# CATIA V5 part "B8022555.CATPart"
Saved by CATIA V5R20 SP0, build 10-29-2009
Part number: B8022555
Revision: 6
Definition: design
Nomenclature: B8022555
Source: made
Description: NOT SPECIFIED
Bounding box of the stored display mesh (mm): x -22.5 to 22.5, y -22.5 to 22.5, z -10 to 55
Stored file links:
  C:\Users\Utente\Desktop\3D files B802\B8022555.CATPart
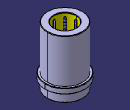
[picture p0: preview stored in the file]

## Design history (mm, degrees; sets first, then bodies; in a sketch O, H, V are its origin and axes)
Body1 "MANIFOLD_SOLID_BREP #38" (main body)
  Solid1: solid without history
Body2 "MANIFOLD_SOLID_BREP #76"
  Solid2: solid without history
Body3 "MANIFOLD_SOLID_BREP #114"
  Solid3: solid without history
Body4 "MANIFOLD_SOLID_BREP #152"
  Solid4: solid without history
Body5 "MANIFOLD_SOLID_BREP #190"
  Solid5: solid without history
Body6 "MANIFOLD_SOLID_BREP #228"
  Solid6: solid without history
Body7 "MANIFOLD_SOLID_BREP #266"
  Solid7: solid without history
Body8 "MANIFOLD_SOLID_BREP #304"
  Solid8: solid without history
Body9 "MANIFOLD_SOLID_BREP #2368"
  Solid9: solid without history
Body10 "MANIFOLD_SOLID_BREP #2406"
  Solid10: solid without history
Body11 "MANIFOLD_SOLID_BREP #2444"
  Solid11: solid without history
Body12 "MANIFOLD_SOLID_BREP #2482"
  Solid12: solid without history
Body13 "MANIFOLD_SOLID_BREP #2520"
  Solid13: solid without history
Body14 "MANIFOLD_SOLID_BREP #2558"
  Solid14: solid without history
Body15 "MANIFOLD_SOLID_BREP #2596"
  Solid15: solid without history
Body16 "MANIFOLD_SOLID_BREP #2634"
  Solid16: solid without history
Body17 "MANIFOLD_SOLID_BREP #2672"
  Solid17: solid without history
Body18 "MANIFOLD_SOLID_BREP #2710"
  Solid18: solid without history
Body19 "MANIFOLD_SOLID_BREP #2748"
  Solid19: solid without history
Body20 "MANIFOLD_SOLID_BREP #2786"
  Solid20: solid without history
Body21 "MANIFOLD_SOLID_BREP #2824"
  Solid21: solid without history
Body22 "MANIFOLD_SOLID_BREP #2862"
  Solid22: solid without history
Body23 "MANIFOLD_SOLID_BREP #2900"
  Solid23: solid without history
Body24 "MANIFOLD_SOLID_BREP #2938"
  Solid24: solid without history
Body25 "MANIFOLD_SOLID_BREP #2976"
  Solid25: solid without history
Body26 "MANIFOLD_SOLID_BREP #3014"
  Solid26: solid without history
Body27 "MANIFOLD_SOLID_BREP #3052"
  Solid27: solid without history
Body28 "MANIFOLD_SOLID_BREP #3090"
  Solid28: solid without history
Body29 "MANIFOLD_SOLID_BREP #3128"
  Solid29: solid without history
Body30 "MANIFOLD_SOLID_BREP #3166"
  Solid30: solid without history
Body31 "MANIFOLD_SOLID_BREP #3204"
  Solid31: solid without history
Body32 "MANIFOLD_SOLID_BREP #3242"
  Solid32: solid without history
Body33 "MANIFOLD_SOLID_BREP #3280"
  Solid33: solid without history
Body34 "MANIFOLD_SOLID_BREP #3318"
  Solid34: solid without history
Body35 "MANIFOLD_SOLID_BREP #3356"
  Solid35: solid without history
Body36 "MANIFOLD_SOLID_BREP #3394"
  Solid36: solid without history
Body37 "MANIFOLD_SOLID_BREP #3432"
  Solid37: solid without history
Body38 "MANIFOLD_SOLID_BREP #3470"
  Solid38: solid without history
Body39 "MANIFOLD_SOLID_BREP #3508"
  Solid39: solid without history
Body40 "MANIFOLD_SOLID_BREP #3546"
  Solid40: solid without history
Body41 "MANIFOLD_SOLID_BREP #3584"
  Solid41: solid without history
Body42 "MANIFOLD_SOLID_BREP #3622"
  Solid42: solid without history
Body43 "MANIFOLD_SOLID_BREP #3660"
  Solid43: solid without history
Body44 "MANIFOLD_SOLID_BREP #3698"
  Solid44: solid without history
Body45 "MANIFOLD_SOLID_BREP #3736"
  Solid45: solid without history
Body46 "MANIFOLD_SOLID_BREP #3774"
  Solid46: solid without history
Body47 "MANIFOLD_SOLID_BREP #3812"
  Solid47: solid without history
Body48 "MANIFOLD_SOLID_BREP #3850"
  Solid48: solid without history
Body49 "MANIFOLD_SOLID_BREP #3888"
  Solid49: solid without history
Body50 "MANIFOLD_SOLID_BREP #3926"
  Solid50: solid without history
Body51 "MANIFOLD_SOLID_BREP #3964"
  Solid51: solid without history
Body52 "MANIFOLD_SOLID_BREP #4002"
  Solid52: solid without history
Body53 "MANIFOLD_SOLID_BREP #4040"
  Solid53: solid without history
Body54 "MANIFOLD_SOLID_BREP #4078"
  Solid54: solid without history
Body55 "MANIFOLD_SOLID_BREP #4116"
  Solid55: solid without history
Body56 "MANIFOLD_SOLID_BREP #4154"
  Solid56: solid without history
Body57 "MANIFOLD_SOLID_BREP #4192"
  Solid57: solid without history
Body58 "MANIFOLD_SOLID_BREP #4230"
  Solid58: solid without history
Body59 "MANIFOLD_SOLID_BREP #4268"
  Solid59: solid without history
Body60 "MANIFOLD_SOLID_BREP #4306"
  Solid60: solid without history
Body61 "MANIFOLD_SOLID_BREP #4344"
  Solid61: solid without history
Body62 "MANIFOLD_SOLID_BREP #4382"
  Solid62: solid without history
Body63 "MANIFOLD_SOLID_BREP #4420"
  Solid63: solid without history
Body64 "MANIFOLD_SOLID_BREP #4458"
  Solid64: solid without history
Body65 "MANIFOLD_SOLID_BREP #4496"
  Solid65: solid without history
Body66 "MANIFOLD_SOLID_BREP #4534"
  Solid66: solid without history
Body67 "MANIFOLD_SOLID_BREP #4572"
  Solid67: solid without history
Body68 "MANIFOLD_SOLID_BREP #4610"
  Solid68: solid without history
Body69 "MANIFOLD_SOLID_BREP #4648"
  Solid69: solid without history
Body70 "MANIFOLD_SOLID_BREP #4686"
  Solid70: solid without history
Body71 "MANIFOLD_SOLID_BREP #4724"
  Solid71: solid without history
Body72 "MANIFOLD_SOLID_BREP #4762"
  Solid72: solid without history
Body73 "MANIFOLD_SOLID_BREP #4800"
  Solid73: solid without history
Body74 "MANIFOLD_SOLID_BREP #4838"
  Solid74: solid without history
Body75 "MANIFOLD_SOLID_BREP #4876"
  Solid75: solid without history
Body76 "MANIFOLD_SOLID_BREP #4914"
  Solid76: solid without history
Body77 "MANIFOLD_SOLID_BREP #4952"
  Solid77: solid without history
Body78 "MANIFOLD_SOLID_BREP #4990"
  Solid78: solid without history
Body79 "MANIFOLD_SOLID_BREP #5028"
  Solid79: solid without history
Body80 "MANIFOLD_SOLID_BREP #5066"
  Solid80: solid without history
Body81 "MANIFOLD_SOLID_BREP #5104"
  Solid81: solid without history
Body82 "MANIFOLD_SOLID_BREP #5142"
  Solid82: solid without history
Body83 "MANIFOLD_SOLID_BREP #5180"
  Solid83: solid without history
Body84 "MANIFOLD_SOLID_BREP #5218"
  Solid84: solid without history
Body85 "MANIFOLD_SOLID_BREP #5256"
  Solid85: solid without history
Body86 "MANIFOLD_SOLID_BREP #5294"
  Solid86: solid without history
Body87 "MANIFOLD_SOLID_BREP #5332"
  Solid87: solid without history
Body88 "MANIFOLD_SOLID_BREP #5370"
  Solid88: solid without history
Body89 "MANIFOLD_SOLID_BREP #5408"
  Solid89: solid without history
Body90 "MANIFOLD_SOLID_BREP #5446"
  Solid90: solid without history
Body91 "MANIFOLD_SOLID_BREP #5484"
  Solid91: solid without history
Body92 "MANIFOLD_SOLID_BREP #5522"
  Solid92: solid without history
Body93 "MANIFOLD_SOLID_BREP #5560"
  Solid93: solid without history
Body94 "MANIFOLD_SOLID_BREP #5598"
  Solid94: solid without history
Body95 "MANIFOLD_SOLID_BREP #5636"
  Solid95: solid without history
Body96 "MANIFOLD_SOLID_BREP #5674"
  Solid96: solid without history
Body97 "MANIFOLD_SOLID_BREP #5712"
  Solid97: solid without history
Body98 "MANIFOLD_SOLID_BREP #5750"
  Solid98: solid without history
Body99 "MANIFOLD_SOLID_BREP #5788"
  Solid99: solid without history
Body100 "MANIFOLD_SOLID_BREP #5826"
  Solid100: solid without history
Body101 "MANIFOLD_SOLID_BREP #5864"
  Solid101: solid without history
Body102 "MANIFOLD_SOLID_BREP #5902"
  Solid102: solid without history
Body103 "MANIFOLD_SOLID_BREP #5940"
  Solid103: solid without history
Body104 "MANIFOLD_SOLID_BREP #5978"
  Solid104: solid without history
Body105 "MANIFOLD_SOLID_BREP #6016"
  Solid105: solid without history
Body106 "MANIFOLD_SOLID_BREP #6054"
  Solid106: solid without history
Body107 "MANIFOLD_SOLID_BREP #6092"
  Solid107: solid without history
Body108 "MANIFOLD_SOLID_BREP #6130"
  Solid108: solid without history
Body109 "MANIFOLD_SOLID_BREP #6168"
  Solid109: solid without history
Body110 "MANIFOLD_SOLID_BREP #6206"
  Solid110: solid without history
Body111 "MANIFOLD_SOLID_BREP #6244"
  Solid111: solid without history
Body112 "MANIFOLD_SOLID_BREP #6282"
  Solid112: solid without history
Body113 "MANIFOLD_SOLID_BREP #6320"
  Solid113: solid without history
Body114 "MANIFOLD_SOLID_BREP #6358"
  Solid114: solid without history
Body115 "MANIFOLD_SOLID_BREP #6396"
  Solid115: solid without history
Body116 "MANIFOLD_SOLID_BREP #6434"
  Solid116: solid without history
Body117 "MANIFOLD_SOLID_BREP #6472"
  Solid117: solid without history
Body118 "MANIFOLD_SOLID_BREP #6510"
  Solid118: solid without history
Body119 "MANIFOLD_SOLID_BREP #6548"
  Solid119: solid without history
Body120 "MANIFOLD_SOLID_BREP #6586"
  Solid120: solid without history
Body121 "MANIFOLD_SOLID_BREP #6624"
  Solid121: solid without history
Body122 "MANIFOLD_SOLID_BREP #6662"
  Solid122: solid without history
Body123 "MANIFOLD_SOLID_BREP #6700"
  Solid123: solid without history
Body124 "MANIFOLD_SOLID_BREP #6738"
  Solid124: solid without history
Body125 "MANIFOLD_SOLID_BREP #6776"
  Solid125: solid without history
Body126 "MANIFOLD_SOLID_BREP #6814"
  Solid126: solid without history
Body127 "MANIFOLD_SOLID_BREP #6852"
  Solid127: solid without history
Body128 "MANIFOLD_SOLID_BREP #6890"
  Solid128: solid without history
Body129 "MANIFOLD_SOLID_BREP #6928"
  Solid129: solid without history
Body130 "MANIFOLD_SOLID_BREP #6966"
  Solid130: solid without history
Body131 "MANIFOLD_SOLID_BREP #7004"
  Solid131: solid without history
Body132 "MANIFOLD_SOLID_BREP #7042"
  Solid132: solid without history
Body133 "MANIFOLD_SOLID_BREP #7080"
  Solid133: solid without history
Body134 "MANIFOLD_SOLID_BREP #7118"
  Solid134: solid without history
Body135 "MANIFOLD_SOLID_BREP #7156"
  Solid135: solid without history
Body136 "MANIFOLD_SOLID_BREP #7194"
  Solid136: solid without history
Body137 "MANIFOLD_SOLID_BREP #7232"
  Solid137: solid without history
Body138 "MANIFOLD_SOLID_BREP #7270"
  Solid138: solid without history
Body139 "MANIFOLD_SOLID_BREP #7308"
  Solid139: solid without history
Body140 "MANIFOLD_SOLID_BREP #7346"
  Solid140: solid without history
Body141 "MANIFOLD_SOLID_BREP #7384"
  Solid141: solid without history
Body142 "MANIFOLD_SOLID_BREP #7422"
  Solid142: solid without history
Body143 "MANIFOLD_SOLID_BREP #7460"
  Solid143: solid without history
Body144 "MANIFOLD_SOLID_BREP #7498"
  Solid144: solid without history
Body145 "MANIFOLD_SOLID_BREP #7536"
  Solid145: solid without history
